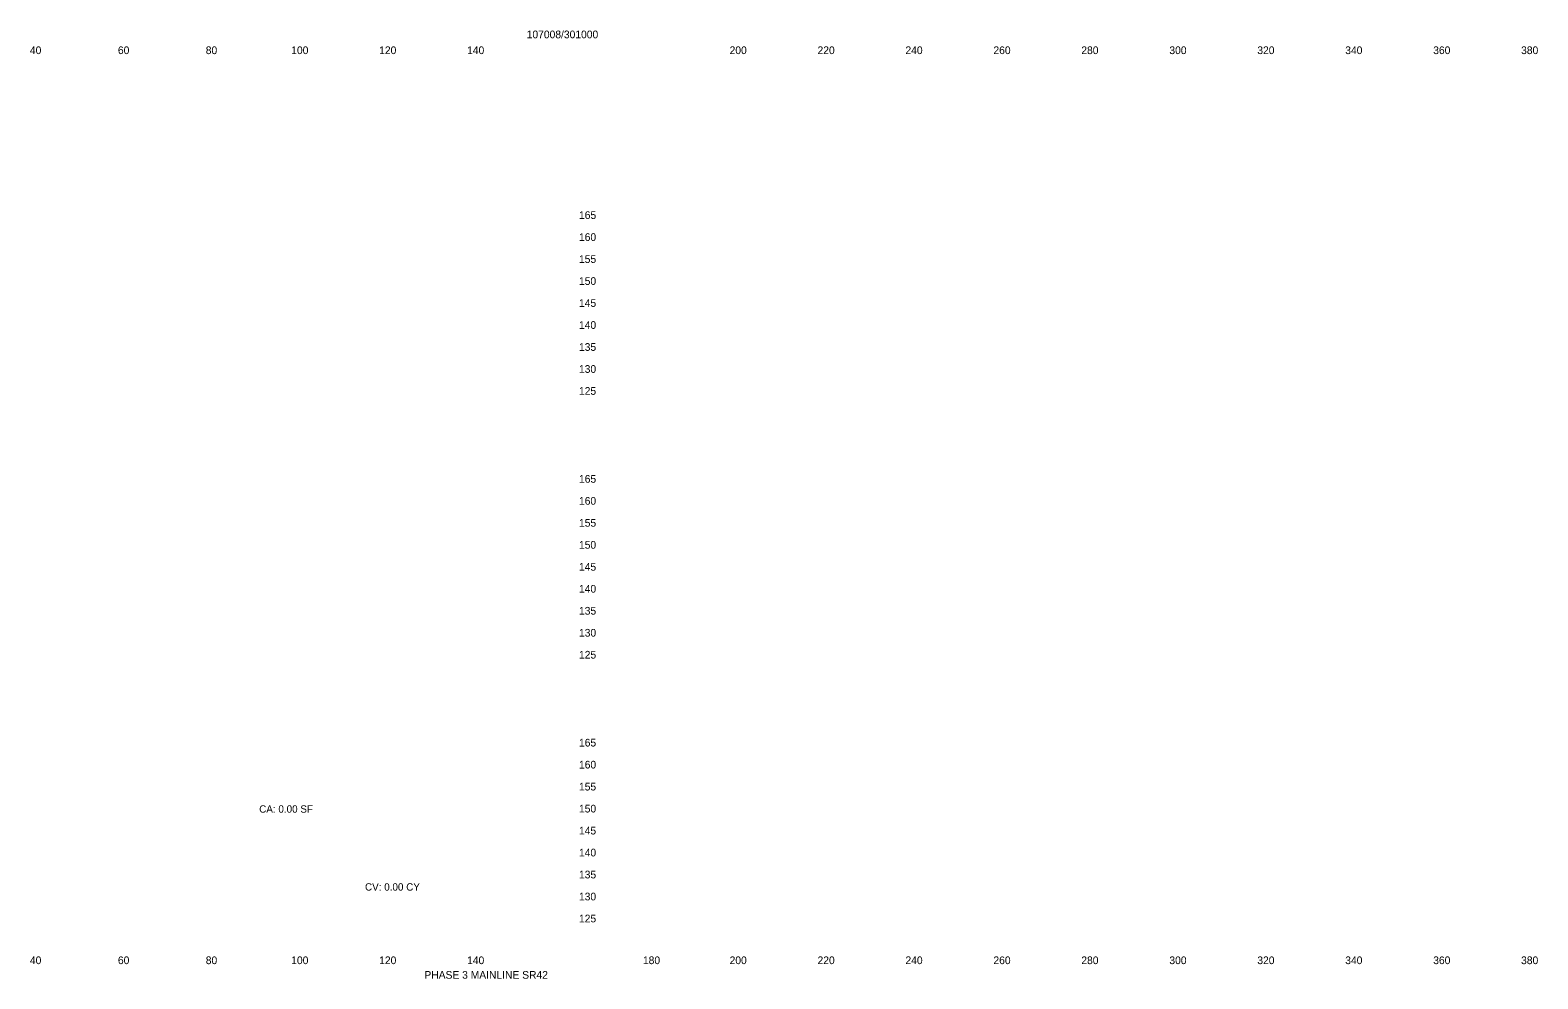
# Model space of a CAD drawing. Extents: x 21281 to 22024, y 6472 to 6918.
# Drawn here: x 21681.3 to 22024.2, y 6702 to 6917.8 of the extents above; entities that cross this region are included whole.
import ezdxf

# ---------------------------------------------------------------- set-up
doc = ezdxf.new("R2010")
doc.units = 0
for name, color, linetype in [('XS_SHEET_EW_TX_AREA', 7, 'Continuous'), ('XS_SHEET_EW_TX_VOLUME', 7, 'Continuous'), ('XS_SHEET_LABELS_OFFSET', 7, 'Continuous'), ('XS_SHEET_LABELS_STATION', 7, 'Continuous')]:
    doc.layers.add(name, color=color, linetype=linetype)

msp = doc.modelspace()

# ---------------------------------------------------------------- texts
at = {"layer": 'XS_SHEET_EW_TX_AREA'}
msp.add_text('CA: 0.00 SF', height=1.68, dxfattribs=at).set_placement((21733.4, 6739.79))
msp.add_text('CA: 0.00 SF', height=1.68, dxfattribs=at).set_placement((21733.4, 6739.79))
at = {"layer": 'XS_SHEET_EW_TX_VOLUME'}
for s, height, p in [('107008/301000', 1.75, (21794.25, 6915.94)), ('  40  ', 1.75, (21679.95, 6912.34)), ('  60  ', 1.75, (21699.97, 6912.34)), ('  80  ', 1.75, (21719.95, 6912.34)), ('  100  ', 1.75, (21739.39, 6912.34)), ('  120  ', 1.75, (21759.39, 6912.34)), ('  165  ', 1.75, (21804.84, 6874.84)), ('  160  ', 1.75, (21804.84, 6869.84)), ('  155  ', 1.75, (21804.84, 6864.84)), ('  150  ', 1.75, (21804.84, 6859.84)), ('  145  ', 1.75, (21804.84, 6854.84)), ('  140  ', 1.75, (21804.84, 6849.84)), ('  135  ', 1.75, (21804.84, 6844.84)), ('  130  ', 1.75, (21804.84, 6839.84)), ('  125  ', 1.75, (21804.84, 6834.84)), ('  165  ', 1.75, (21804.84, 6814.84)), ('  160  ', 1.75, (21804.84, 6809.84)), ('  155  ', 1.75, (21804.84, 6804.84)), ('  150  ', 1.75, (21804.84, 6799.84)), ('  145  ', 1.75, (21804.84, 6794.84)), ('  140  ', 1.75, (21804.84, 6789.84)), ('  135  ', 1.75, (21804.84, 6784.84)), ('  130  ', 1.75, (21804.84, 6779.84)), ('  125  ', 1.75, (21804.84, 6774.84)), ('  165  ', 1.75, (21804.84, 6754.84)), ('  160  ', 1.75, (21804.84, 6749.84)), ('  155  ', 1.75, (21804.84, 6744.84)), ('  150  ', 1.75, (21804.84, 6739.84)), ('  145  ', 1.75, (21804.84, 6734.84)), ('  140  ', 1.75, (21804.84, 6729.84)), ('  135  ', 1.75, (21804.84, 6724.84)), ('CV: 0.00 CY', 1.68, (21757.47, 6722.06)), ('  130  ', 1.75, (21804.84, 6719.84)), ('  125  ', 1.75, (21804.84, 6714.84)), ('  40  ', 1.75, (21679.95, 6705.34)), ('  60  ', 1.75, (21699.97, 6705.34)), ('  80  ', 1.75, (21719.95, 6705.34)), ('  100  ', 1.75, (21739.39, 6705.34)), ('  120  ', 1.75, (21759.39, 6705.34)), ('  140  ', 1.75, (21779.39, 6705.34)), ('PHASE 3 MAINLINE SR42', 1.75, (21770.98, 6702.02))]:
    msp.add_text(s, height=height, dxfattribs=at).set_placement(p)
at = {"layer": 'XS_SHEET_LABELS_OFFSET'}
for s, p in [('  260  ', (21899.11, 6912.34)), ('  280  ', (21919.1, 6912.34)), ('  300  ', (21939.13, 6912.34)), ('  320  ', (21959.13, 6912.34)), ('  340  ', (21979.13, 6912.34)), ('  360  ', (21999.14, 6912.34)), ('  380  ', (22019.13, 6912.34)), ('  180  ', (21819.39, 6705.34)), ('  200  ', (21839.1, 6705.34)), ('  220  ', (21859.1, 6705.34)), ('  240  ', (21879.1, 6705.34)), ('  260  ', (21899.11, 6705.34)), ('  280  ', (21919.1, 6705.34)), ('  300  ', (21939.13, 6705.34)), ('  320  ', (21959.13, 6705.34)), ('  340  ', (21979.13, 6705.34)), ('  360  ', (21999.14, 6705.34)), ('  380  ', (22019.13, 6705.34))]:
    msp.add_text(s, height=1.75, dxfattribs=at).set_placement(p)
at = {"layer": 'XS_SHEET_LABELS_STATION'}
for s, p in [('  140  ', (21779.39, 6912.34)), ('  200  ', (21839.1, 6912.34)), ('  220  ', (21859.1, 6912.34)), ('  240  ', (21879.1, 6912.34))]:
    msp.add_text(s, height=1.75, dxfattribs=at).set_placement(p)

doc.saveas('drawing.dxf')
